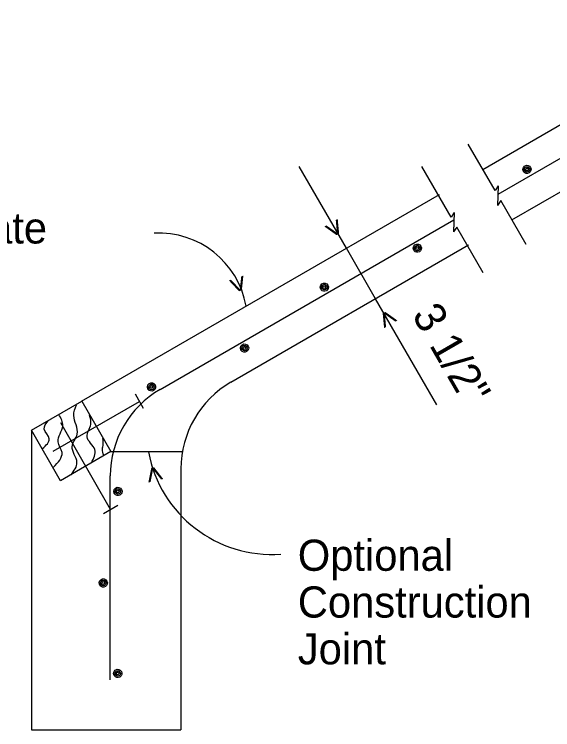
# Model space of a CAD drawing. Extents: x 0 to 3.31, y -0.03 to 1.83.
# Drawn here: x 0.3128 to 0.5376, y 0.1549 to 0.4535 of the extents above; entities that cross this region are included whole.
import ezdxf

# ---------------------------------------------------------------- set-up
doc = ezdxf.new("R2010")
doc.units = 0
for name, color, linetype in [('50', 7, 'Continuous'), ('51', 7, 'Continuous'), ('55', 7, 'Continuous'), ('57', 7, 'Continuous')]:
    doc.layers.add(name, color=color, linetype=linetype)

msp = doc.modelspace()

# ---------------------------------------------------------------- linework, layer by layer
at = {"layer": '50'}
for p, q in [((0.5148198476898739, 0.3783922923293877), (0.6825948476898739, 0.47525895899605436)), ((0.5084615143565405, 0.38875895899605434), (0.5760615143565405, 0.4277922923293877)), ((0.5206115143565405, 0.3677089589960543), (0.5882115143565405, 0.4067422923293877)), ((0.5148781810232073, 0.3819422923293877), (0.5135531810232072, 0.37993395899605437)), ((0.5148781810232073, 0.3819422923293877), (0.5146281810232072, 0.3737589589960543)), ((0.34091151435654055, 0.292025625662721), (0.49037818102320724, 0.378325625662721)), ((0.5147365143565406, 0.37785062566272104), (0.5147365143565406, 0.37785062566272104)), ((0.5159448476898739, 0.375775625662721), (0.5146281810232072, 0.3737589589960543)), ((0.49651151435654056, 0.3708672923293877), (0.49518651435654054, 0.36885895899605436)), ((0.49651151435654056, 0.3708672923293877), (0.49626151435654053, 0.3626839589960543)), ((0.3737281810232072, 0.2969422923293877), (0.4963948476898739, 0.3677589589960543)), ((0.4975781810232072, 0.364700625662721), (0.49626151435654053, 0.3626839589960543)), ((0.49636984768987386, 0.36677562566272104), (0.49636984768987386, 0.36677562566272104)), ((0.403234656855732, 0.2999368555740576), (0.5025365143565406, 0.35727562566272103)), ((0.3199115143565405, 0.279900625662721), (0.3199115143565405, 0.15490895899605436)), ((0.3824031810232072, 0.26385353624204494), (0.3824031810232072, 0.15490895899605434)), ((0.3199115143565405, 0.15490895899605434), (0.3824031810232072, 0.15490895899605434))]:
    msp.add_line(p, q, dxfattribs=at)
msp.add_lwpolyline([(0.3320615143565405, 0.258850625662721), (0.3199115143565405, 0.279900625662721), (0.34096151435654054, 0.292050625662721), (0.35311151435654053, 0.271000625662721)], close=True, dxfattribs=at)
msp.add_arc((0.4240698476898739, 0.26385353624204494), 0.04166666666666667, 120.00294943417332, 180, dxfattribs=at)
at = {"layer": '51'}
for p, q in [((0.5269056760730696, 0.38878979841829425), (0.5269056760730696, 0.38878979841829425)), ((0.5269056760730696, 0.38878979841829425), (0.5269056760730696, 0.38878979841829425)), ((0.48111151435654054, 0.3558922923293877), (0.48111151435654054, 0.3558922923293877)), ((0.48111151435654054, 0.3558922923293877), (0.48111151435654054, 0.3558922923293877)), ((0.4422531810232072, 0.3396422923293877), (0.4422531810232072, 0.3396422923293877)), ((0.4422531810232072, 0.3396422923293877), (0.4422531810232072, 0.3396422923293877)), ((0.4089448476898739, 0.314225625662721), (0.4089448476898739, 0.314225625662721)), ((0.4089448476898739, 0.314225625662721), (0.4089448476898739, 0.314225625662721)), ((0.37008651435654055, 0.297975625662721), (0.37008651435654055, 0.297975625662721)), ((0.37008651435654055, 0.297975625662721), (0.37008651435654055, 0.297975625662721)), ((0.3668115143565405, 0.2889422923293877), (0.36334484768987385, 0.294950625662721)), ((0.32899484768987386, 0.27110895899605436), (0.3650781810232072, 0.2919422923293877)), ((0.3530031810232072, 0.24688395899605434), (0.3321698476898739, 0.28296729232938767)), ((0.3528948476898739, 0.17574229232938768), (0.3528948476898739, 0.260850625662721)), ((0.3560448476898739, 0.2543634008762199), (0.3560448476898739, 0.2543634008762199)), ((0.3560448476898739, 0.2543634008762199), (0.3560448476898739, 0.2543634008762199)), ((0.3499948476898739, 0.245150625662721), (0.35601151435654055, 0.24861729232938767)), ((0.3499445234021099, 0.21614154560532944), (0.3499445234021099, 0.21614154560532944)), ((0.3499445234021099, 0.21614154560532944), (0.3499445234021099, 0.21614154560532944)), ((0.3560107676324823, 0.17839602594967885), (0.3560107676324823, 0.17839602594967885)), ((0.3560107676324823, 0.17839602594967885), (0.3560107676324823, 0.17839602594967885))]:
    msp.add_line(p, q, dxfattribs=at)
for points in [[(0.5254056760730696, 0.3879314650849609), (0.5251806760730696, 0.38881479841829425), (0.5254056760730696, 0.3896231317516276), (0.5258723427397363, 0.3901731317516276), (0.526639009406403, 0.3905064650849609), (0.527339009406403, 0.39047313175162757), (0.5279473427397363, 0.3901731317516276), (0.5284223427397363, 0.3896231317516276), (0.528639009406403, 0.38892313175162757), (0.5285640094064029, 0.3882731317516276), (0.528289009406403, 0.38773979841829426), (0.5277890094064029, 0.3872981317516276), (0.527139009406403, 0.3870731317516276), (0.5265556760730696, 0.38710646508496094), (0.5259890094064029, 0.38731479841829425), (0.5256223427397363, 0.38763146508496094), (0.5254306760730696, 0.3878814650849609), (0.5258223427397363, 0.3883981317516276), (0.525764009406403, 0.38896479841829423), (0.526064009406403, 0.3895647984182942), (0.5266473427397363, 0.3899064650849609), (0.5272806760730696, 0.38988979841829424), (0.527814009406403, 0.3895064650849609), (0.528064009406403, 0.3887564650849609), (0.5279056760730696, 0.3881981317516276), (0.5274640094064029, 0.3877814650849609), (0.5269056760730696, 0.38763146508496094), (0.5264140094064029, 0.38773979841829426), (0.5260223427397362, 0.3880314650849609), (0.5258223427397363, 0.3883814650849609), (0.5263306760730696, 0.3888481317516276), (0.5264973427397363, 0.38918146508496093), (0.5268473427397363, 0.3893564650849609), (0.527239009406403, 0.3892481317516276), (0.5274723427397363, 0.3888231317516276), (0.5273556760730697, 0.38842313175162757), (0.5269890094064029, 0.3882231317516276), (0.5265723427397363, 0.3883231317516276), (0.5263556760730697, 0.38861479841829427), (0.5263223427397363, 0.38883979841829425)], [(0.47961151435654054, 0.35503395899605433), (0.47938651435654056, 0.3559172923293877), (0.4796031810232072, 0.35673395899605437), (0.4800698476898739, 0.35727562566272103), (0.48083651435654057, 0.3576089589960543), (0.4815448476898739, 0.357575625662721), (0.4821531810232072, 0.35728395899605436), (0.4826281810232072, 0.35672562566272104), (0.48283651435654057, 0.35603395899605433), (0.48276984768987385, 0.35538395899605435), (0.48248651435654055, 0.354850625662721), (0.48198651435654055, 0.354400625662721), (0.48133651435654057, 0.35417562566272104), (0.4807531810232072, 0.35420895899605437), (0.48018651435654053, 0.354425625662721), (0.4798198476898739, 0.35473395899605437), (0.47963651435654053, 0.35498395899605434), (0.4800281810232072, 0.355500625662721), (0.4799698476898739, 0.35606729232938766), (0.4802615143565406, 0.356675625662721), (0.48085318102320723, 0.35701729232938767), (0.4814781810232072, 0.3569922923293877), (0.4820198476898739, 0.35661729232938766), (0.4822615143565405, 0.35585895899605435), (0.48211151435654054, 0.35530895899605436), (0.48166984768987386, 0.35488395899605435), (0.48111151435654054, 0.3547422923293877), (0.48061984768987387, 0.354850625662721), (0.4802281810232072, 0.3551339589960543), (0.4800198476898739, 0.35548395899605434), (0.48053651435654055, 0.355950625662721), (0.4807031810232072, 0.35628395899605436), (0.4810531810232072, 0.35645895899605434), (0.48143651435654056, 0.35635895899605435), (0.4816781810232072, 0.355925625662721), (0.48156151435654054, 0.35553395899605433), (0.48119484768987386, 0.35533395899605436), (0.4807698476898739, 0.35543395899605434), (0.48056151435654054, 0.35572562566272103), (0.4805281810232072, 0.3559422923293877)], [(0.4407531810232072, 0.33878395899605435), (0.44052818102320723, 0.3396672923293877), (0.4407448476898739, 0.340475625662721), (0.44121151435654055, 0.341025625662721), (0.44198651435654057, 0.34135895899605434), (0.44268651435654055, 0.341325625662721), (0.44329484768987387, 0.341025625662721), (0.4437698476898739, 0.340475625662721), (0.4439865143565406, 0.339775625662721), (0.4439115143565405, 0.33912562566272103), (0.44363651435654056, 0.3385922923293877), (0.44313651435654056, 0.338150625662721), (0.4424865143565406, 0.337925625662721), (0.4419031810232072, 0.3379589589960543), (0.4413281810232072, 0.3381672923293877), (0.4409698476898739, 0.3384839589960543), (0.4407781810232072, 0.33873395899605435), (0.4411698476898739, 0.339250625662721), (0.44111151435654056, 0.3398172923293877), (0.4414031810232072, 0.34041729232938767), (0.4419948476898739, 0.34075895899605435), (0.4426198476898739, 0.3407422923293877), (0.44316151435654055, 0.34035895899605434), (0.4434115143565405, 0.33960895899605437), (0.4432531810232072, 0.339050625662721), (0.44281151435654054, 0.33863395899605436), (0.4422531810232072, 0.3384839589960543), (0.44176151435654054, 0.3385922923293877), (0.44136984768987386, 0.33888395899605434), (0.4411698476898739, 0.33923395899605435), (0.4416781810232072, 0.339700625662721), (0.44184484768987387, 0.3400339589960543), (0.4421948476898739, 0.34020895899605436), (0.44258651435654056, 0.34010062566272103), (0.44281984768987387, 0.339675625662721), (0.4427031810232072, 0.339275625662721), (0.44233651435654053, 0.33907562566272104), (0.44191984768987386, 0.339175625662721), (0.4417031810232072, 0.33946729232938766), (0.4416698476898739, 0.3396922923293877)], [(0.40743651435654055, 0.3133672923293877), (0.40721151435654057, 0.314250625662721), (0.40743651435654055, 0.3150672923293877), (0.4079031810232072, 0.31560895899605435), (0.40866984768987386, 0.3159422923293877), (0.4093781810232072, 0.31590895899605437), (0.4099781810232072, 0.3156172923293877), (0.41046151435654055, 0.31505895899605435), (0.41066984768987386, 0.3143672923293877), (0.41059484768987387, 0.31371729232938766), (0.4103198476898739, 0.31318395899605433), (0.4098198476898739, 0.31273395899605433), (0.40916984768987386, 0.31250895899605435), (0.40858651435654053, 0.3125422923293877), (0.40801984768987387, 0.3127589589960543), (0.4076531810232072, 0.3130672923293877), (0.40746151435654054, 0.31331729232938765), (0.4078531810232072, 0.3138339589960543), (0.4077948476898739, 0.31440062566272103), (0.40809484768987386, 0.31500895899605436), (0.4086865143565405, 0.315350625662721), (0.40931151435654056, 0.315325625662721), (0.4098531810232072, 0.31495062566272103), (0.41009484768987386, 0.31419229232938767), (0.40993651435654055, 0.3136422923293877), (0.4095031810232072, 0.31321729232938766), (0.40893651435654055, 0.313075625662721), (0.4084531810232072, 0.31318395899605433), (0.4080531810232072, 0.3134672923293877), (0.4078531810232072, 0.31381729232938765), (0.4083698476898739, 0.3142839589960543), (0.4085281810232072, 0.3146172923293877), (0.40888651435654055, 0.31479229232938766), (0.4092698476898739, 0.31469229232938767), (0.40951151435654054, 0.3142589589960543), (0.4093948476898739, 0.3138672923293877), (0.40901984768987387, 0.31366729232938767), (0.4086031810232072, 0.31376729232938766), (0.40838651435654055, 0.31405895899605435), (0.4083531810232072, 0.314275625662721)], [(0.36858651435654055, 0.29711729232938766), (0.3683531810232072, 0.298000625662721), (0.3685781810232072, 0.29880895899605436), (0.3690448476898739, 0.29935895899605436), (0.3698115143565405, 0.29969229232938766), (0.3705198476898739, 0.2996589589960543), (0.3711198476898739, 0.29935895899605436), (0.3716031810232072, 0.29880895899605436), (0.37181151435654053, 0.29810895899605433), (0.37173651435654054, 0.29745895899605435), (0.37146151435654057, 0.296925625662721), (0.37096151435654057, 0.29648395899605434), (0.3703115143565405, 0.29625895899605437), (0.3697281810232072, 0.2962922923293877), (0.36916151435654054, 0.296500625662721), (0.36879484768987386, 0.2968172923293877), (0.3686031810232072, 0.29706729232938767), (0.3690031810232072, 0.29758395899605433), (0.36893651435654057, 0.298150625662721), (0.36923651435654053, 0.29875062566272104), (0.3698281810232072, 0.29909229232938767), (0.37045318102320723, 0.299075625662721), (0.3709948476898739, 0.29869229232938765), (0.37123651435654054, 0.2979422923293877), (0.37108651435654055, 0.29738395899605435), (0.3706448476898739, 0.2969672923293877), (0.37008651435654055, 0.2968172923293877), (0.3695948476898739, 0.296925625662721), (0.3691948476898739, 0.29721729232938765), (0.3689948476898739, 0.29756729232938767), (0.36951151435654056, 0.29803395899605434), (0.3696698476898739, 0.2983672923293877), (0.3700281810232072, 0.29854229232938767), (0.3704115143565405, 0.29843395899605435), (0.3706531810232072, 0.29800895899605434), (0.37053651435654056, 0.29760895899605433), (0.3701698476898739, 0.29740895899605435), (0.36974484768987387, 0.29750895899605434), (0.3695281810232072, 0.29780062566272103), (0.3694948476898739, 0.298025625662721)], [(0.3545448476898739, 0.25350506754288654), (0.35431151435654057, 0.2543884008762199), (0.35453651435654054, 0.2551967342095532), (0.3550031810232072, 0.25574673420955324), (0.35576984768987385, 0.25608006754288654), (0.3564781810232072, 0.2560467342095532), (0.3570781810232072, 0.25574673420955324), (0.35756151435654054, 0.2551967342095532), (0.35776984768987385, 0.2544967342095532), (0.35769484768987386, 0.2538467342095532), (0.3574198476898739, 0.2533134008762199), (0.3569198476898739, 0.2528717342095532), (0.35626984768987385, 0.2526467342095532), (0.35568651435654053, 0.2526800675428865), (0.35511984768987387, 0.2528884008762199), (0.3547531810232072, 0.2532050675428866), (0.35456151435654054, 0.25345506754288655), (0.35496151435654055, 0.2539717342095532), (0.3548948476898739, 0.2545384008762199), (0.35519484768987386, 0.25513840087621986), (0.3557865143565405, 0.25548006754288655), (0.35641151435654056, 0.2554634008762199), (0.3569531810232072, 0.25508006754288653), (0.35719484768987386, 0.25433006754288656), (0.3570448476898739, 0.25377173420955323), (0.3566031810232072, 0.25335506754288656), (0.3560448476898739, 0.2532050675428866), (0.3555531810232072, 0.2533134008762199), (0.3551531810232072, 0.25360506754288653), (0.3549531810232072, 0.25395506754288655), (0.3554698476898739, 0.2544217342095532), (0.3556281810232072, 0.25475506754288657), (0.35598651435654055, 0.25493006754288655), (0.3563698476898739, 0.25482173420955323), (0.35661151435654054, 0.2543967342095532), (0.3564948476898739, 0.2539967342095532), (0.3561281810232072, 0.25379673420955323), (0.3557031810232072, 0.2538967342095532), (0.35548651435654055, 0.25418840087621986), (0.3554531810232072, 0.2544134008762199)], [(0.3484445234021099, 0.2152832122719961), (0.3482111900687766, 0.21616654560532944), (0.3484361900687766, 0.21697487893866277), (0.34890285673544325, 0.21752487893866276), (0.34966952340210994, 0.21785821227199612), (0.35037785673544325, 0.21782487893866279), (0.3509778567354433, 0.21752487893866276), (0.3514611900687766, 0.21697487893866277), (0.35166952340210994, 0.21627487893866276), (0.35159452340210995, 0.21562487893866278), (0.3513195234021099, 0.21509154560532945), (0.3508195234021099, 0.21464987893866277), (0.35016952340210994, 0.21442487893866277), (0.3495861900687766, 0.2144582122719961), (0.34901952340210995, 0.21466654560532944), (0.3486528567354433, 0.2149832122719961), (0.3484611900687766, 0.2152332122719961), (0.3488611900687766, 0.21574987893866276), (0.3487945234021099, 0.21631654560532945), (0.34909452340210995, 0.21691654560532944), (0.3496861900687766, 0.2172582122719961), (0.3503111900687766, 0.21724154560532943), (0.35085285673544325, 0.21685821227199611), (0.35109452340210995, 0.21610821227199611), (0.3509445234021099, 0.2155498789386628), (0.3505028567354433, 0.2151332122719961), (0.3499445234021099, 0.2149832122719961), (0.34945285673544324, 0.21509154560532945), (0.3490528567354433, 0.2153832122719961), (0.34885285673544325, 0.2157332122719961), (0.3493695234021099, 0.21619987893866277), (0.3495278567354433, 0.2165332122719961), (0.3498861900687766, 0.2167082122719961), (0.35026952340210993, 0.21659987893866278), (0.3505111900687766, 0.21617487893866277), (0.3503945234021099, 0.21577487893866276), (0.3500278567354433, 0.21557487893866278), (0.3496028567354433, 0.21567487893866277), (0.3493861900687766, 0.21596654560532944), (0.34935285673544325, 0.21619154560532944)], [(0.3545107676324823, 0.17753769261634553), (0.35427743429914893, 0.17842102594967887), (0.35450243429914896, 0.1792293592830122), (0.35496910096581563, 0.1797793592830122), (0.35573576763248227, 0.18011269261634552), (0.35644410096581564, 0.1800793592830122), (0.3570441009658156, 0.1797793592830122), (0.35752743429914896, 0.1792293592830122), (0.35773576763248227, 0.1785293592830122), (0.3576607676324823, 0.17787935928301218), (0.35738576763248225, 0.17734602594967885), (0.35688576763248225, 0.1769043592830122), (0.35623576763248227, 0.1766793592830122), (0.35565243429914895, 0.17671269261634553), (0.3550857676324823, 0.17692102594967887), (0.3547191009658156, 0.17723769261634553), (0.35452743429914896, 0.17748769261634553), (0.35492743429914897, 0.1780043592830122), (0.35486076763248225, 0.17857102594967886), (0.3551607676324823, 0.17917102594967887), (0.35575243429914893, 0.17951269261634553), (0.3563774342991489, 0.17949602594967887), (0.35691910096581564, 0.17911269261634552), (0.3571607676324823, 0.17836269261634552), (0.3570107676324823, 0.1778043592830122), (0.3565691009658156, 0.17738769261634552), (0.3560107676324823, 0.17723769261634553), (0.3555191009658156, 0.17734602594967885), (0.3551191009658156, 0.17763769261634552), (0.35491910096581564, 0.17798769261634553), (0.3554357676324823, 0.1784543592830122), (0.3555941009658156, 0.17878769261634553), (0.35595243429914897, 0.17896269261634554), (0.35633576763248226, 0.1788543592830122), (0.35657743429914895, 0.1784293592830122), (0.3564607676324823, 0.1780293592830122), (0.3560941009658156, 0.1778293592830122), (0.3556691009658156, 0.1779293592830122), (0.35545243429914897, 0.17822102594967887), (0.35541910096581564, 0.17844602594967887)]]:
    msp.add_lwpolyline(points, dxfattribs=at)
msp.add_arc((0.3945622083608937, 0.2608541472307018), 0.04166666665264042, 120.000125, 180, dxfattribs=at)
at = {"layer": '55'}
for p, q in [((0.5135531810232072, 0.37993395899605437), (0.5023865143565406, 0.399275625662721)), ((0.45146984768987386, 0.35585895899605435), (0.43172007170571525, 0.39007291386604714)), ((0.49518651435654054, 0.36885895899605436), (0.4829781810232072, 0.39000895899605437)), ((0.5265031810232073, 0.35750895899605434), (0.5159531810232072, 0.375775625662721)), ((0.5085698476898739, 0.34568395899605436), (0.49758651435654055, 0.364700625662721)), ((0.46361984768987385, 0.33480895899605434), (0.45146984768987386, 0.35585895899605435)), ((0.4891938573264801, 0.2905052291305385), (0.46361984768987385, 0.33480895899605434))]:
    msp.add_line(p, q, dxfattribs=at)
for centre, radius, start, end in [((0.3732402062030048, 0.3253113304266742), 0.03688865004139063, 9.987354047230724, 93.25357071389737), ((0.4203527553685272, 0.2804677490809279), 0.052404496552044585, 190.5379638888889, 274.1448416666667)]:
    msp.add_arc(centre, radius, start, end, dxfattribs=at)
for points in [[(0.33646984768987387, 0.26124229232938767), (0.33896984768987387, 0.2664839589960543), (0.33693651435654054, 0.273050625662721), (0.3390531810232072, 0.2782922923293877), (0.33764484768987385, 0.28611729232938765), (0.33873651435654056, 0.290575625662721)], [(0.3245031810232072, 0.2722672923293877), (0.32739484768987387, 0.27633395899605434), (0.32528651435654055, 0.28040895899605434), (0.3270031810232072, 0.284000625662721)], [(0.3291198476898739, 0.264450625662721), (0.33271151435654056, 0.270625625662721), (0.33106984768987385, 0.27508395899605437), (0.3330281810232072, 0.28173395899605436), (0.33138651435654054, 0.28650895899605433)], [(0.3449948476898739, 0.266325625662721), (0.3464031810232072, 0.271800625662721), (0.34319484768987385, 0.277200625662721), (0.34476151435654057, 0.28235895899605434), (0.3441365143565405, 0.2862672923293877)], [(0.3501531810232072, 0.269375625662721), (0.34961151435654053, 0.2720339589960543), (0.3499198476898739, 0.2740672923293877), (0.3497615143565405, 0.27641729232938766)]]:
    msp.add_spline(points, degree=3, dxfattribs=at)
at = {"layer": '57'}
msp.add_line((0.35311151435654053, 0.271000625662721), (0.3830207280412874, 0.271000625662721), dxfattribs=at)

# ---------------------------------------------------------------- texts
at = {"layer": '55'}
for height, rotation, p in [(0.008672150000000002, 300.013425, (0.44121151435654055, 0.3649672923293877)), (0.008672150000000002, 300.013425, (0.44121151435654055, 0.3649672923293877)), (0.0086711, 288.5477863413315, (0.4013219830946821, 0.34267950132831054)), (0.0086711, 288.5477863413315, (0.4013219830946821, 0.34267950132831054)), (0.008672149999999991, 120.013425, (0.4738781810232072, 0.325700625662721)), (0.008672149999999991, 120.013425, (0.4738781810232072, 0.325700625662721)), (0.008675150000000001, 103.32453055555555, (0.37604878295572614, 0.25921698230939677)), (0.008675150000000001, 103.32453055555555, (0.37604878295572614, 0.25921698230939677))]:
    msp.add_text('>', height=height, rotation=rotation, dxfattribs=at).set_placement(p)
at = {"layer": '57'}
for s, p in [('Aggregate', (0.24613649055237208, 0.3578542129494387)), ('Optional ', (0.4311987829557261, 0.22123397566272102)), ('Construction', (0.4311987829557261, 0.2017089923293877)), ('Joint', (0.4311987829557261, 0.18218400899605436))]:
    msp.add_text(s, height=0.013016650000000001, dxfattribs=at).set_placement(p)
msp.add_text('3 1/2"', height=0.013016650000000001, rotation=299.99364722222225, dxfattribs=at).set_placement((0.4786281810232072, 0.3280621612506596))

doc.saveas('drawing.dxf')
